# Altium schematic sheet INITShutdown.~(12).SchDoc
size A4
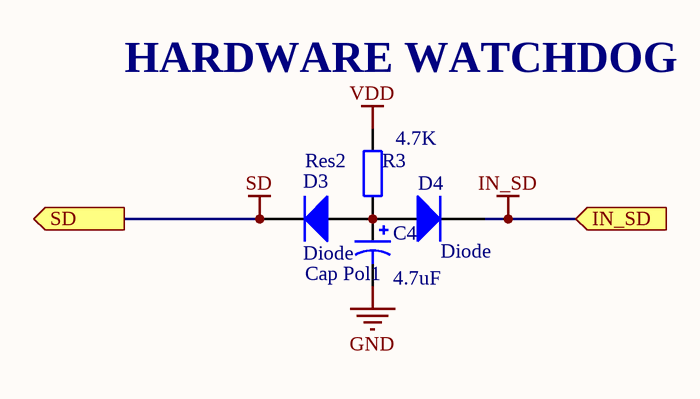
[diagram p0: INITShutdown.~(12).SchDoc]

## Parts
C4  Cap Pol1  value 4.7uF  [CAPPR2.5-6.3X5]
D3  Diode  [DO-204AL]
D4  Diode  [DO-204AL]
R3  Res2  value 4.7K  [AXIAL-0.3]

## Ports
IN_SD (in), SD (out)

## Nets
GND: C4.2
IN_SD: D4.2(K) ; port IN_SD
SD: D3.2(K) ; port SD
VDD: R3.2
NetC4_1: C4.1 D3.1(A) D4.1(A) R3.1

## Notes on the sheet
- (near R3) HARDWARE WATCHDOG

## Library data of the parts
C4 = Cap Pol1: Polarized Capacitor (Radial)
D3 D4 = Diode: 1n4148
R3 = Res2: Resistor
